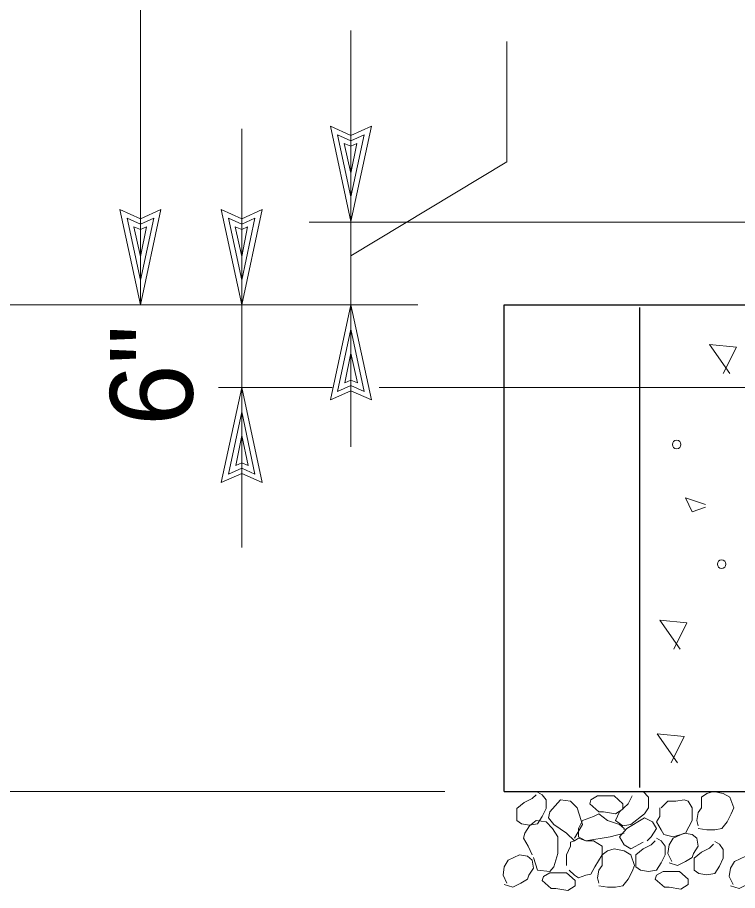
# Model space of a CAD drawing. Extents: x -22.3 to 19.7, y -11.8 to 18.2.
# Drawn here: x -18.723 to -17.635, y -8.544 to -7.223 of the extents above; entities that cross this region are included whole.
import ezdxf
from ezdxf.enums import TextEntityAlignment as Align

# ---------------------------------------------------------------- set-up
doc = ezdxf.new("R2010")
doc.units = 0
doc.header["$LTSCALE"] = 0.05
doc.layers.add('1', color=7, linetype='Continuous', lineweight=13)
doc.layers.add('2', color=7, linetype='Continuous', lineweight=13)

msp = doc.modelspace()

# ---------------------------------------------------------------- linework, layer by layer
at = {"layer": '1'}
for p, q in [((-18.53742, -7.65769), (-18.53742, -4.99969)), ((-18.21942, -7.53169), (-18.25042, -7.38769)), ((-18.21942, -7.53169), (-18.18842, -7.38769)), ((-18.21942, -7.49469), (-18.23942, -7.40069)), ((-18.23942, -7.40069), (-18.21942, -7.40969)), ((-18.21942, -7.49469), (-18.19942, -7.40069)), ((-18.21942, -7.40969), (-18.19942, -7.40069)), ((-18.21942, -7.45869), (-18.22942, -7.41369)), ((-18.22942, -7.41369), (-18.21942, -7.41769)), ((-18.21942, -7.45869), (-18.21042, -7.41369)), ((-18.21942, -7.41769), (-18.21042, -7.41369)), ((-18.53742, -7.65769), (-18.56842, -7.51369)), ((-18.53742, -7.65769), (-18.50642, -7.51369)), ((-18.38442, -7.65769), (-18.41542, -7.51369)), ((-18.38442, -7.65769), (-18.35342, -7.51369)), ((-18.53742, -7.62069), (-18.55742, -7.52669)), ((-18.55742, -7.52669), (-18.53742, -7.53569)), ((-18.53742, -7.62069), (-18.51742, -7.52669)), ((-18.53742, -7.53569), (-18.51742, -7.52669)), ((-18.38442, -7.62069), (-18.40442, -7.52669)), ((-18.40442, -7.52669), (-18.38442, -7.53569)), ((-18.38442, -7.62069), (-18.36442, -7.52669)), ((-18.38442, -7.53569), (-18.36442, -7.52669)), ((-18.53742, -7.58469), (-18.54742, -7.53969)), ((-18.54742, -7.53969), (-18.53742, -7.54369)), ((-18.53742, -7.58469), (-18.52842, -7.53969)), ((-18.53742, -7.54369), (-18.52842, -7.53969)), ((-18.38442, -7.58469), (-18.39442, -7.53969)), ((-18.39442, -7.53969), (-18.38442, -7.54369)), ((-18.38442, -7.58469), (-18.37542, -7.53969)), ((-18.38442, -7.54369), (-18.37542, -7.53969)), ((-5.69442, -7.53269), (-18.28242, -7.53269)), ((-18.11842, -7.65769), (-19.34842, -7.65769)), ((-18.21942, -7.65769), (-18.25042, -7.80169)), ((-18.21942, -7.65769), (-18.18842, -7.80169)), ((-18.21942, -7.69469), (-18.23942, -7.78869)), ((-18.21942, -7.69469), (-18.19942, -7.78869)), ((-18.21942, -7.73069), (-18.22842, -7.77569)), ((-18.21942, -7.73069), (-18.20942, -7.77569)), ((-18.21942, -7.77169), (-18.22842, -7.77569)), ((-18.20942, -7.77569), (-18.21942, -7.77169)), ((-18.24742, -7.78269), (-18.41942, -7.78269)), ((-18.38442, -7.78269), (-18.41542, -7.92669)), ((-18.38442, -7.78269), (-18.35342, -7.92669)), ((-18.21942, -7.77969), (-18.23942, -7.78869)), ((-18.19942, -7.78869), (-18.21942, -7.77969)), ((-16.96442, -7.78269), (-18.17642, -7.78269)), ((-18.38442, -7.81969), (-18.40442, -7.91369)), ((-18.38442, -7.81969), (-18.36442, -7.91369)), ((-18.38442, -7.85569), (-18.39342, -7.90069)), ((-18.38442, -7.85569), (-18.37442, -7.90069)), ((-18.38442, -7.89669), (-18.39342, -7.90069)), ((-18.37442, -7.90069), (-18.38442, -7.89669)), ((-18.38442, -7.90469), (-18.40442, -7.91369)), ((-18.36442, -7.91369), (-18.38442, -7.90469)), ((-18.07742, -8.39369), (-19.34842, -8.39369))]:
    msp.add_line(p, q, dxfattribs=at)
at = {"layer": '1', "lineweight": 25}
for p, q in [((-17.98742, -8.39369), (-17.98742, -7.65769)), ((-17.98742, -7.65769), (-16.90342, -7.65769)), ((-17.78242, -8.38769), (-17.78242, -7.66169)), ((-17.98742, -8.39369), (-16.77042, -8.39369))]:
    msp.add_line(p, q, dxfattribs=at)
at = {"layer": '1'}
for points in [[(-18.21942, -7.87269), (-18.21942, -7.65769), (-18.21942, -7.53169), (-18.21942, -7.24269)], [(-18.21942, -7.58369), (-17.98342, -7.44169), (-17.98342, -7.25969)], [(-18.38442, -8.02469), (-18.38442, -7.78269), (-18.38442, -7.65769), (-18.38442, -7.39169)], [(-18.25042, -7.38769), (-18.21942, -7.40169), (-18.18842, -7.38769)], [(-18.56842, -7.51369), (-18.53742, -7.52769), (-18.50642, -7.51369)], [(-18.41542, -7.51369), (-18.38442, -7.52769), (-18.35342, -7.51369)], [(-18.18842, -7.80169), (-18.21942, -7.78769), (-18.25042, -7.80169)], [(-18.35342, -7.92669), (-18.38442, -7.91269), (-18.41542, -7.92669)], [(-17.93942, -8.39869), (-17.94542, -8.40469), (-17.95742, -8.41069), (-17.96842, -8.41969), (-17.96842, -8.42969), (-17.96842, -8.43769), (-17.96142, -8.44269), (-17.94942, -8.44469), (-17.93742, -8.44269), (-17.93042, -8.43169), (-17.92442, -8.41969), (-17.92442, -8.40669), (-17.93042, -8.39869), (-17.93742, -8.39469)], [(-17.79442, -8.40069), (-17.80042, -8.41269), (-17.81342, -8.42469), (-17.81942, -8.43769), (-17.80842, -8.44569), (-17.79642, -8.44369), (-17.77542, -8.42769), (-17.76942, -8.41869), (-17.76942, -8.40269), (-17.77742, -8.39369), (-17.78842, -8.39369)], [(-17.69442, -8.44569), (-17.69642, -8.43769), (-17.69442, -8.42569), (-17.68942, -8.41869), (-17.68942, -8.40269), (-17.68142, -8.39669), (-17.67142, -8.39369), (-17.65642, -8.39669), (-17.64642, -8.40269), (-17.64042, -8.41869), (-17.64442, -8.42769), (-17.65042, -8.43969), (-17.65842, -8.44969), (-17.66942, -8.45169), (-17.68142, -8.45169), (-17.69442, -8.44969)], [(-17.88142, -8.46869), (-17.89342, -8.45669), (-17.91242, -8.44369), (-17.92042, -8.43369), (-17.91842, -8.42469), (-17.90242, -8.40669), (-17.88742, -8.40869), (-17.87742, -8.41869), (-17.87142, -8.43769), (-17.86942, -8.44369), (-17.88142, -8.46469)], [(-17.75242, -8.41869), (-17.75242, -8.43169), (-17.75742, -8.43969), (-17.75042, -8.45169), (-17.74642, -8.45869), (-17.73242, -8.46269), (-17.71342, -8.45669), (-17.70342, -8.43769), (-17.70342, -8.42769), (-17.70342, -8.41869), (-17.70942, -8.40869), (-17.71542, -8.40669), (-17.72842, -8.40869), (-17.74042, -8.40869), (-17.75042, -8.41869)], [(-17.94542, -8.48969), (-17.95142, -8.47669), (-17.95842, -8.46469), (-17.95642, -8.45669), (-17.94942, -8.44569), (-17.93942, -8.43769), (-17.92442, -8.43969), (-17.91442, -8.44969), (-17.90642, -8.46269), (-17.90642, -8.48769), (-17.91242, -8.50769), (-17.91842, -8.51469), (-17.93742, -8.51269), (-17.94342, -8.49369)], [(-17.80642, -8.45669), (-17.82742, -8.46269), (-17.86442, -8.46869), (-17.87542, -8.46269), (-17.87542, -8.44969), (-17.86942, -8.43769), (-17.85242, -8.43169), (-17.84442, -8.42769), (-17.83142, -8.43769), (-17.82542, -8.43969), (-17.81342, -8.44369), (-17.80642, -8.44969), (-17.80642, -8.45169)], [(-17.77742, -8.47069), (-17.79642, -8.48069), (-17.80642, -8.47469), (-17.81342, -8.46269), (-17.80242, -8.44969), (-17.77542, -8.43369), (-17.76342, -8.43969), (-17.75742, -8.44969), (-17.76542, -8.46269), (-17.77142, -8.46869)], [(-17.73442, -8.49969), (-17.74042, -8.48769), (-17.73842, -8.47469), (-17.73242, -8.46469), (-17.71542, -8.45669), (-17.70342, -8.45869), (-17.69642, -8.46469), (-17.69442, -8.47669), (-17.70142, -8.48769), (-17.70342, -8.49369), (-17.71342, -8.49969), (-17.72542, -8.50569), (-17.73842, -8.50169)], [(-17.89342, -8.50569), (-17.89342, -8.49569), (-17.89342, -8.48969), (-17.88742, -8.47669), (-17.88742, -8.47069), (-17.88142, -8.46869), (-17.87542, -8.46469), (-17.86442, -8.46869), (-17.85242, -8.46869), (-17.83942, -8.47669), (-17.83942, -8.48969), (-17.85042, -8.50769), (-17.85642, -8.51869), (-17.86442, -8.52069), (-17.87542, -8.52469), (-17.88142, -8.52069), (-17.88942, -8.51269)], [(-17.75942, -8.46869), (-17.76542, -8.47469), (-17.77742, -8.48069), (-17.78842, -8.48969), (-17.78842, -8.49969), (-17.78842, -8.50769), (-17.78142, -8.51269), (-17.76942, -8.51469), (-17.75742, -8.51269), (-17.75042, -8.50169), (-17.74442, -8.48969), (-17.74442, -8.47669), (-17.75042, -8.46869), (-17.75742, -8.46469)], [(-17.67142, -8.47369), (-17.67742, -8.47969), (-17.68942, -8.48569), (-17.70042, -8.49469), (-17.70042, -8.50469), (-17.70042, -8.51269), (-17.69342, -8.51769), (-17.68142, -8.51969), (-17.66942, -8.51769), (-17.66242, -8.50669), (-17.65642, -8.49469), (-17.65642, -8.48169), (-17.66242, -8.47369), (-17.66942, -8.46969)], [(-17.98342, -8.53269), (-17.98942, -8.52069), (-17.98742, -8.50769), (-17.98142, -8.49769), (-17.96442, -8.48969), (-17.95242, -8.49169), (-17.94542, -8.49769), (-17.94342, -8.50969), (-17.95042, -8.52069), (-17.95242, -8.52669), (-17.96242, -8.53269), (-17.97442, -8.53869), (-17.98742, -8.53469)], [(-17.84442, -8.53269), (-17.84642, -8.52469), (-17.84442, -8.51269), (-17.83942, -8.50569), (-17.83942, -8.48969), (-17.83142, -8.48369), (-17.82142, -8.48069), (-17.80642, -8.48369), (-17.79642, -8.48969), (-17.79042, -8.50569), (-17.79442, -8.51469), (-17.80042, -8.52669), (-17.80842, -8.53669), (-17.81942, -8.53869), (-17.83142, -8.53869), (-17.84442, -8.53669)], [(-17.64142, -8.53469), (-17.64742, -8.52269), (-17.64542, -8.50969), (-17.63942, -8.49969), (-17.62242, -8.49169), (-17.61042, -8.49369), (-17.60342, -8.49969), (-17.60142, -8.51169), (-17.60842, -8.52269), (-17.61042, -8.52869), (-17.62042, -8.53469), (-17.63242, -8.54069), (-17.64542, -8.53669)]]:
    msp.add_lwpolyline(points, dxfattribs=at)
for points in [[(-17.85842, -8.41269), (-17.84442, -8.42469), (-17.83742, -8.42469), (-17.81942, -8.42769), (-17.80842, -8.42069), (-17.80842, -8.41269), (-17.82142, -8.40069), (-17.83142, -8.40069), (-17.84642, -8.40069), (-17.85642, -8.40669)], [(-17.93042, -8.52869), (-17.91642, -8.54069), (-17.90942, -8.54069), (-17.89142, -8.54369), (-17.88042, -8.53669), (-17.88042, -8.52869), (-17.89342, -8.51669), (-17.90342, -8.51669), (-17.91842, -8.51669), (-17.92842, -8.52269)], [(-17.75942, -8.52669), (-17.74542, -8.53869), (-17.73842, -8.53869), (-17.72042, -8.54169), (-17.70942, -8.53469), (-17.70942, -8.52669), (-17.72242, -8.51469), (-17.73242, -8.51469), (-17.74742, -8.51469), (-17.75742, -8.52069)]]:
    msp.add_lwpolyline(points, close=True, dxfattribs=at)
at = {"layer": '2'}
for points in [[(-17.65642, -7.76169), (-17.63642, -7.72169), (-17.67742, -7.71769), (-17.64642, -7.76169)], [(-17.68342, -7.96369), (-17.70342, -7.97069), (-17.71342, -7.94969), (-17.68342, -7.95969)], [(-17.73142, -8.17869), (-17.71142, -8.13869), (-17.75242, -8.13469), (-17.72142, -8.17869)], [(-17.73542, -8.35069), (-17.71542, -8.31069), (-17.75642, -8.30669), (-17.72542, -8.35069)]]:
    msp.add_lwpolyline(points, dxfattribs=at)
for centre in [(-17.72692, -7.86919), (-17.65892, -8.05019)]:
    msp.add_circle(centre, 0.0065, dxfattribs=at)

# ---------------------------------------------------------------- texts
at = {"layer": '1'}
msp.add_text('6"', height=0.125, rotation=90, dxfattribs=at).set_placement((-18.45842, -7.76469), align=Align.CENTER)

doc.saveas('drawing.dxf')
